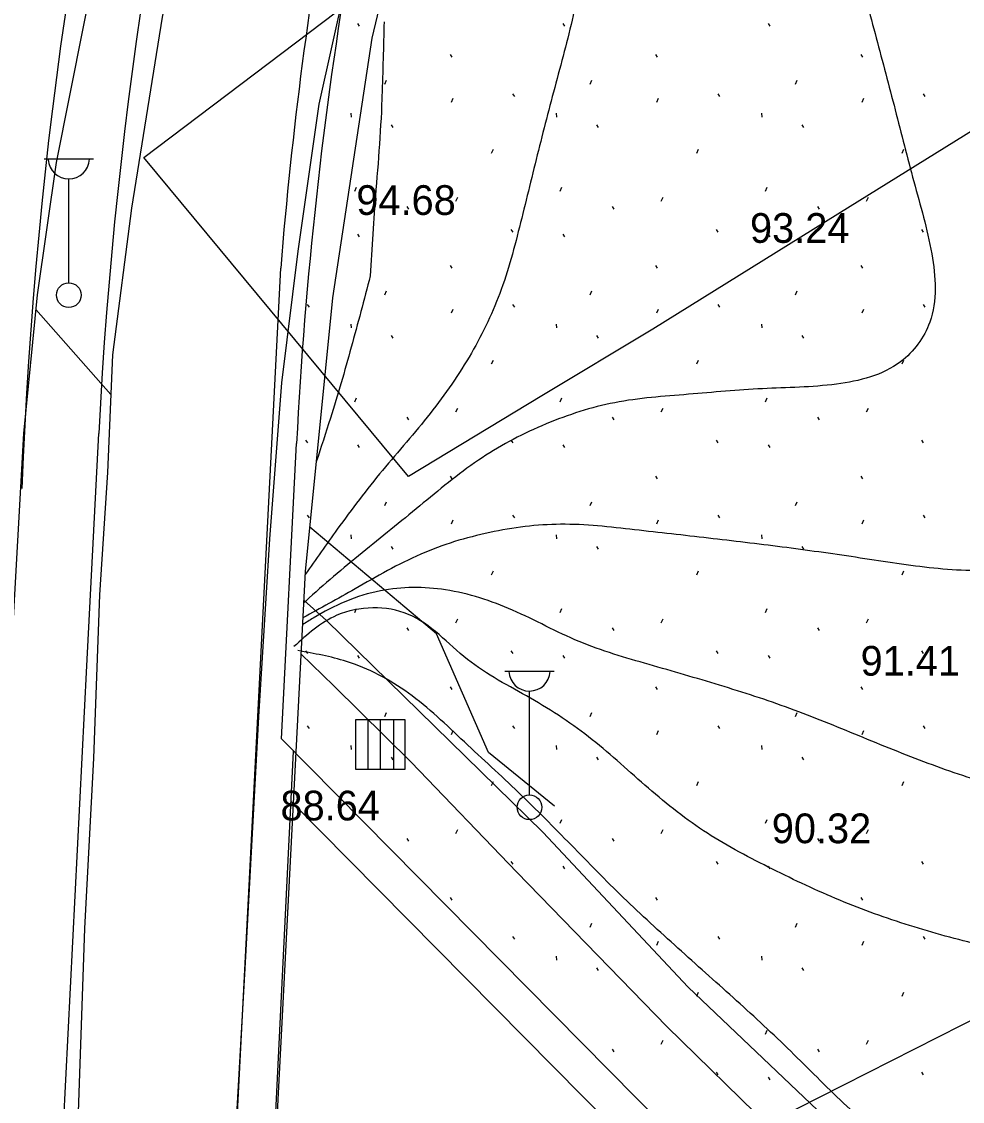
# Model space of a CAD drawing. Extents: x 412225 to 413380, y 4456471 to 4457189.
# Drawn here: x 412668.22 to 412706.22, y 4456722.27 to 4456765.88 of the extents above; entities that cross this region are included whole.
import ezdxf

# ---------------------------------------------------------------- set-up
doc = ezdxf.new("R2010")
doc.units = 0
for name, color, linetype in [('0_HALİHAZIR', 7, 'Continuous'), ('0_KADASTRO', 7, 'Continuous'), ('Level 41', 7, 'Continuous'), ('Level 62', 7, 'Continuous')]:
    doc.layers.add(name, color=color, linetype=linetype)

msp = doc.modelspace()

# ---------------------------------------------------------------- linework, layer by layer
at = {"layer": '0_HALİHAZIR'}
for p, q in [((412669.131, 4456760.333), (412671.131, 4456760.333)), ((412670.131, 4456755.333), (412670.131, 4456759.526)), ((412682.492, 4456758.569), (412682.308, 4456755.611)), ((412687.738, 4456739.651), (412689.738, 4456739.651)), ((412688.738, 4456734.651), (412688.738, 4456738.844)), ((412683.717, 4456737.684), (412681.717, 4456737.684)), ((412681.717, 4456737.684), (412681.717, 4456735.684)), ((412683.717, 4456737.684), (412681.717, 4456737.684)), ((412681.717, 4456737.684), (412681.717, 4456735.684)), ((412682.222, 4456735.684), (412682.222, 4456737.684)), ((412682.717, 4456735.684), (412682.717, 4456737.684)), ((412683.265, 4456735.684), (412683.265, 4456737.684)), ((412683.717, 4456735.684), (412683.717, 4456737.684)), ((412683.717, 4456735.684), (412683.717, 4456737.684)), ((412681.717, 4456735.684), (412683.717, 4456735.684)), ((412681.717, 4456735.684), (412683.717, 4456735.684))]:
    msp.add_line(p, q, dxfattribs=at)
for points in [[(412667.705, 4456738.404), (412668.319, 4456749.244), (412668.861, 4456754.841), (412669.638, 4456760.194), (412671.826, 4456771.222), (412673.519, 4456777.969), (412675.417, 4456784.177), (412677.82, 4456790.656), (412680.764, 4456798.407), (412683.199, 4456803.834), (412686.955, 4456811.642), (412691.094, 4456818.38), (412696.148, 4456825.735), (412699.773, 4456830.686), (412704.115, 4456836.108), (412708.688, 4456841.501), (412715.879, 4456848.789), (412726.186, 4456857.727), (412735.602, 4456865.198), (412750.205, 4456876.525), (412762.02, 4456885.738), (412775.183, 4456895.99), (412775.364, 4456896.141)], [(412684.648, 4456799.81), (412681.991, 4456793.804), (412680.12, 4456789.142), (412678.212, 4456783.624), (412676.557, 4456777.683), (412674.837, 4456770.524), (412673.9, 4456766.056), (412672.665, 4456758.345), (412671.898, 4456752.417), (412671.688, 4456747.664), (412671.366, 4456742.728), (412671.134, 4456736.134), (412670.758, 4456729.258), (412670.505, 4456721.841)], [(412742.95, 4456768.054), (412742.709, 4456772.16), (412741.745, 4456776.255), (412740.013, 4456781.161), (412737.651, 4456785.317), (412735.352, 4456788.538), (412732.317, 4456791.501), (412728.579, 4456794.241), (412724.985, 4456796.111), (412720.885, 4456797.711), (412716.226, 4456798.251), (412711.867, 4456798.434), (412706.537, 4456797.665), (412702.626, 4456796.458), (412698.189, 4456794.174), (412694.709, 4456791.591), (412690.527, 4456787.602), (412688.224, 4456784.396), (412687.256, 4456781.998), (412683.814, 4456771.248), (412682.374, 4456765.211), (412680.786, 4456754.718)], [(412697.453, 4456795.517), (412694.9, 4456793.639), (412691.148, 4456790.576), (412688.107, 4456787.244), (412686.438, 4456784.458), (412685.05, 4456780.461), (412683.352, 4456775.225), (412681.838, 4456769.746), (412680.234, 4456762.54), (412679.384, 4456756.61), (412678.722, 4456751.292), (412678.239, 4456744.989), (412677.786, 4456737.8), (412677.257, 4456727.881), (412676.433, 4456713.438)], [(412680.786, 4456754.718), (412679.682, 4456743.672), (412678.182, 4456714.804), (412676.891, 4456689.605), (412675.965, 4456668.667), (412674.91, 4456650.901), (412674.029, 4456632.544), (412673.304, 4456622.54), (412672.579, 4456615.955), (412671.095, 4456608.422), (412669.559, 4456601.069)], [(412671.827, 4456750.815), (412668.804, 4456754.253)], [(412744.221, 4456750.848), (412744.627, 4456745.627), (412744.52, 4456741.68), (412744.187, 4456738.618), (412743.007, 4456735.034), (412741.225, 4456731.014), (412738.205, 4456726.236), (412735.858, 4456723.736), (412732.659, 4456721.076), (412728.924, 4456719.082), (412724.248, 4456717.386), (412720.135, 4456716.553), (412714.255, 4456716.237), (412710.318, 4456716.87), (412705.381, 4456718.359), (412702.879, 4456719.736), (412700.365, 4456721.918), (412695.148, 4456726.887), (412689.271, 4456733.146), (412680.533, 4456741.696), (412679.621, 4456742.512)], [(412689.751, 4456734.194), (412687.089, 4456736.357), (412684.981, 4456741.158), (412679.86, 4456745.461)], [(412680.836, 4456739.057), (412679.509, 4456740.353)], [(412688.233, 4456731.526), (412683.96, 4456735.967), (412680.836, 4456739.057)], [(412688.233, 4456731.526), (412694.29, 4456725.303), (412698.443, 4456721.239)]]:
    msp.add_lwpolyline(points, dxfattribs=at)
for centre in [(412670.131, 4456754.833), (412688.738, 4456734.151)]:
    msp.add_circle(centre, 0.5, dxfattribs=at)
for centre in [(412670.131, 4456760.363), (412688.738, 4456739.681)]:
    msp.add_arc(centre, 0.837, 183.298, 356.9072, dxfattribs=at)
for points in [[(412704.847, 4456799.043), (412705.974, 4456796.274), (412707.165, 4456793.522), (412708.403, 4456790.789), (412709.584, 4456788.033), (412710.679, 4456785.242), (412711.666, 4456782.41), (412712.542, 4456779.544), (412713.326, 4456776.649), (412714.047, 4456773.737), (412714.748, 4456770.82), (412715.437, 4456767.9), (412716.115, 4456764.978), (412716.737, 4456762.044), (412717.218, 4456759.09), (412717.479, 4456756.11), (412717.34, 4456753.142), (412716.635, 4456750.305), (412715.242, 4456747.748), (412713.201, 4456745.661), (412710.668, 4456744.282), (412707.846, 4456743.729), (412704.882, 4456743.826), (412701.912, 4456744.245), (412698.942, 4456744.659), (412695.964, 4456745.019), (412692.983, 4456745.358), (412689.997, 4456745.579), (412687.132, 4456745.247), (412684.343, 4456744.37), (412681.692, 4456742.971), (412679.584, 4456741.797)], [(412695.675, 4456794.209), (412696.043, 4456791.246), (412696.342, 4456788.264), (412696.806, 4456785.324), (412697.548, 4456782.447), (412698.52, 4456779.61), (412699.468, 4456776.765), (412700.337, 4456773.894), (412701.167, 4456771.011), (412701.965, 4456768.119), (412702.742, 4456765.222), (412703.508, 4456762.321), (412704.263, 4456759.418), (412704.983, 4456756.506), (412704.904, 4456753.738), (412703.727, 4456752.143), (412701.142, 4456751.24), (412698.148, 4456751.055), (412695.157, 4456750.827), (412692.179, 4456750.49), (412689.408, 4456749.631), (412686.828, 4456748.268), (412684.45, 4456746.44), (412682.125, 4456744.545), (412679.841, 4456742.606), (412679.616, 4456742.397)], [(412731.677, 4456792.764), (412730.692, 4456789.931), (412729.801, 4456787.069), (412729.109, 4456784.16), (412728.851, 4456781.21), (412729.104, 4456778.277), (412729.838, 4456775.384), (412730.8, 4456772.544), (412731.778, 4456769.709), (412732.574, 4456766.828), (412732.856, 4456763.906), (412732.642, 4456760.965), (412732.023, 4456758.031), (412731.319, 4456755.115), (412730.582, 4456752.207), (412729.81, 4456749.308), (412728.974, 4456746.428), (412727.897, 4456743.648), (412726.427, 4456741.094), (412724.426, 4456738.95), (412722.007, 4456737.271), (412719.303, 4456736.01), (412716.459, 4456735.098), (412713.534, 4456734.546), (412710.577, 4456734.497), (412707.677, 4456735.005), (412704.835, 4456735.924), (412702.048, 4456737.034), (412699.259, 4456738.14), (412696.419, 4456739.078), (412693.569, 4456739.915), (412690.743, 4456740.845), (412688.057, 4456742.109), (412685.351, 4456742.931), (412682.725, 4456742.895), (412680.002, 4456741.793), (412679.57, 4456741.518)], [(412687.47, 4456780.884), (412688.574, 4456778.095), (412689.663, 4456775.299), (412690.551, 4456772.446), (412690.867, 4456769.607), (412690.606, 4456766.674), (412689.901, 4456763.759), (412689.145, 4456760.856), (412688.423, 4456757.945), (412687.6, 4456755.067), (412686.391, 4456752.494), (412684.724, 4456750.052), (412682.799, 4456747.755), (412680.974, 4456745.378), (412679.675, 4456743.547)], [(412682.863, 4456765.868), (412682.78, 4456762.873), (412682.776, 4456762.759), (412682.492, 4456758.569)], [(412745.325, 4456760.007), (412744.674, 4456757.08), (412743.93, 4456754.173), (412743.171, 4456751.271), (412742.421, 4456748.366), (412739.332, 4456740.016), (412738.051, 4456737.304), (412736.799, 4456734.578), (412735.403, 4456731.923), (412730.489, 4456728.959), (412727.571, 4456728.261), (412724.67, 4456727.498), (412718.811, 4456726.642), (412715.827, 4456726.941), (412712.857, 4456727.363), (412709.907, 4456727.907), (412706.982, 4456728.574), (412704.091, 4456729.374), (412701.272, 4456730.396), (412698.548, 4456731.652), (412695.923, 4456733.103), (412693.541, 4456734.919), (412691.275, 4456736.881), (412688.784, 4456738.552), (412686.229, 4456740.125), (412683.848, 4456741.941), (412680.963, 4456741.903), (412679.22, 4456740.639)], [(412682.308, 4456755.611), (412681.537, 4456752.727), (412680.695, 4456749.859), (412680.124, 4456748.102)], [(412726.577, 4456718.634), (412723.677, 4456717.874), (412720.747, 4456717.289), (412717.774, 4456716.956), (412714.8, 4456717.011), (412711.836, 4456717.352), (412708.916, 4456718.02), (412706.106, 4456718.981), (412703.552, 4456720.437), (412701.29, 4456722.332), (412699.154, 4456724.429), (412696.964, 4456726.464), (412694.732, 4456728.464), (412692.535, 4456730.5), (412690.421, 4456732.628), (412688.299, 4456734.749), (412686.108, 4456736.792), (412683.849, 4456738.76), (412681.341, 4456740.04), (412679.384, 4456740.477)]]:
    msp.add_spline(points, degree=3, dxfattribs=at)
at = {"layer": '0_KADASTRO'}
for points in [[(412673.155, 4456760.386), (412710.52, 4456788.649), (412718.832, 4456794.936), (412724.702, 4456799.376), (412733.822, 4456806.36), (412736.373, 4456808.313), (412748.14, 4456817.324), (412752.117, 4456820.369), (412752.765, 4456820.865), (412764.736, 4456830.001), (412767.728, 4456825.718), (412770.674, 4456821.667), (412779.346, 4456806.615), (412763.366, 4456796.695), (412758.704, 4456793.802), (412755.666, 4456791.916), (412701.697, 4456758.415), (412693.721, 4456753.465), (412689.243, 4456750.764), (412683.853, 4456747.515)], [(412691.873, 4456718.1), (412706.213, 4456725.36), (412710.904, 4456727.735), (412715.66, 4456730.142), (412730.796, 4456737.805), (412731.276, 4456736.996), (412735.606, 4456729.684), (412742.529, 4456717.995), (412747.23, 4456710.057), (412729.251, 4456700.211), (412717.055, 4456693.532)]]:
    msp.add_lwpolyline(points, close=True, dxfattribs=at)
at = {"layer": 'Level 41'}
for p, q in [((412681.794, 4456765.806), (412681.865, 4456765.699)), ((412690.087, 4456765.806), (412690.158, 4456765.699)), ((412698.38, 4456765.806), (412698.451, 4456765.699)), ((412685.532, 4456764.545), (412685.603, 4456764.438)), ((412693.825, 4456764.545), (412693.896, 4456764.438)), ((412702.118, 4456764.545), (412702.189, 4456764.438)), ((412682.891, 4456763.352), (412682.962, 4456763.511)), ((412691.184, 4456763.352), (412691.255, 4456763.511)), ((412699.477, 4456763.352), (412699.548, 4456763.511)), ((412685.59, 4456762.623), (412685.662, 4456762.783)), ((412688.055, 4456762.968), (412688.126, 4456762.861)), ((412693.883, 4456762.623), (412693.955, 4456762.783)), ((412696.348, 4456762.968), (412696.419, 4456762.861)), ((412702.176, 4456762.623), (412702.248, 4456762.783)), ((412704.641, 4456762.968), (412704.712, 4456762.861)), ((412681.52, 4456762.177), (412681.538, 4456762.017)), ((412689.813, 4456762.177), (412689.831, 4456762.017)), ((412698.106, 4456762.177), (412698.124, 4456762.017)), ((412683.15, 4456761.707), (412683.22, 4456761.6)), ((412691.443, 4456761.707), (412691.513, 4456761.6)), ((412699.736, 4456761.707), (412699.806, 4456761.6)), ((412687.206, 4456760.563), (412687.278, 4456760.723)), ((412695.499, 4456760.563), (412695.571, 4456760.723)), ((412703.792, 4456760.563), (412703.864, 4456760.723)), ((412681.685, 4456759.033), (412681.755, 4456759.193)), ((412689.978, 4456759.033), (412690.048, 4456759.193)), ((412698.271, 4456759.033), (412698.341, 4456759.193)), ((412685.768, 4456758.625), (412685.839, 4456758.785)), ((412694.061, 4456758.625), (412694.132, 4456758.785)), ((412702.354, 4456758.625), (412702.425, 4456758.785)), ((412683.78, 4456758.417), (412683.851, 4456758.311)), ((412692.073, 4456758.417), (412692.144, 4456758.311)), ((412700.366, 4456758.417), (412700.437, 4456758.311)), ((412687.988, 4456757.488), (412688.059, 4456757.381)), ((412696.281, 4456757.488), (412696.352, 4456757.381)), ((412704.574, 4456757.488), (412704.645, 4456757.381)), ((412681.794, 4456757.296), (412681.865, 4456757.189)), ((412690.087, 4456757.296), (412690.158, 4456757.189)), ((412698.38, 4456757.296), (412698.451, 4456757.189)), ((412685.532, 4456756.035), (412685.603, 4456755.928)), ((412693.825, 4456756.035), (412693.896, 4456755.928)), ((412702.118, 4456756.035), (412702.189, 4456755.928)), ((412682.891, 4456754.842), (412682.962, 4456755.001)), ((412691.184, 4456754.842), (412691.255, 4456755.001)), ((412699.477, 4456754.842), (412699.548, 4456755.001)), ((412679.762, 4456754.458), (412679.833, 4456754.351)), ((412685.59, 4456754.113), (412685.662, 4456754.273)), ((412688.055, 4456754.458), (412688.126, 4456754.351)), ((412693.883, 4456754.113), (412693.955, 4456754.273)), ((412696.348, 4456754.458), (412696.419, 4456754.351)), ((412702.176, 4456754.113), (412702.248, 4456754.273)), ((412704.641, 4456754.458), (412704.712, 4456754.351)), ((412681.52, 4456753.667), (412681.538, 4456753.507)), ((412689.813, 4456753.667), (412689.831, 4456753.507)), ((412698.106, 4456753.667), (412698.124, 4456753.507)), ((412683.15, 4456753.197), (412683.22, 4456753.09)), ((412691.443, 4456753.197), (412691.513, 4456753.09)), ((412699.736, 4456753.197), (412699.806, 4456753.09)), ((412687.206, 4456752.053), (412687.278, 4456752.213)), ((412695.499, 4456752.053), (412695.571, 4456752.213)), ((412703.792, 4456752.053), (412703.864, 4456752.213)), ((412681.685, 4456750.523), (412681.755, 4456750.683)), ((412689.978, 4456750.523), (412690.048, 4456750.683)), ((412698.271, 4456750.523), (412698.341, 4456750.683)), ((412683.78, 4456749.907), (412683.851, 4456749.801)), ((412685.768, 4456750.115), (412685.839, 4456750.275)), ((412692.073, 4456749.907), (412692.144, 4456749.801)), ((412694.061, 4456750.115), (412694.132, 4456750.275)), ((412700.366, 4456749.907), (412700.437, 4456749.801)), ((412702.354, 4456750.115), (412702.425, 4456750.275)), ((412679.695, 4456748.978), (412679.766, 4456748.871)), ((412681.794, 4456748.786), (412681.865, 4456748.679)), ((412687.988, 4456748.978), (412688.059, 4456748.871)), ((412690.087, 4456748.786), (412690.158, 4456748.679)), ((412696.281, 4456748.978), (412696.352, 4456748.871)), ((412698.38, 4456748.786), (412698.451, 4456748.679)), ((412704.574, 4456748.978), (412704.645, 4456748.871)), ((412685.532, 4456747.525), (412685.603, 4456747.418)), ((412693.825, 4456747.525), (412693.896, 4456747.418)), ((412702.118, 4456747.525), (412702.189, 4456747.418)), ((412682.891, 4456746.332), (412682.962, 4456746.491)), ((412691.184, 4456746.332), (412691.255, 4456746.491)), ((412699.477, 4456746.332), (412699.548, 4456746.491)), ((412679.762, 4456745.948), (412679.833, 4456745.841)), ((412685.59, 4456745.603), (412685.662, 4456745.763)), ((412688.055, 4456745.948), (412688.126, 4456745.841)), ((412693.883, 4456745.603), (412693.955, 4456745.763)), ((412696.348, 4456745.948), (412696.419, 4456745.841)), ((412702.176, 4456745.603), (412702.248, 4456745.763)), ((412704.641, 4456745.948), (412704.712, 4456745.841)), ((412681.52, 4456745.157), (412681.538, 4456744.997)), ((412689.813, 4456745.157), (412689.831, 4456744.997)), ((412698.106, 4456745.157), (412698.124, 4456744.997)), ((412683.15, 4456744.687), (412683.22, 4456744.58)), ((412691.443, 4456744.687), (412691.513, 4456744.58)), ((412699.736, 4456744.687), (412699.806, 4456744.58)), ((412687.206, 4456743.543), (412687.278, 4456743.703)), ((412695.499, 4456743.543), (412695.571, 4456743.703)), ((412703.792, 4456743.543), (412703.864, 4456743.703)), ((412681.685, 4456742.013), (412681.755, 4456742.173)), ((412689.978, 4456742.013), (412690.048, 4456742.173)), ((412698.271, 4456742.013), (412698.341, 4456742.173)), ((412685.768, 4456741.605), (412685.839, 4456741.765)), ((412694.061, 4456741.605), (412694.132, 4456741.765)), ((412702.354, 4456741.605), (412702.425, 4456741.765)), ((412683.78, 4456741.397), (412683.851, 4456741.291)), ((412692.073, 4456741.397), (412692.144, 4456741.291)), ((412700.366, 4456741.397), (412700.437, 4456741.291)), ((412679.695, 4456740.468), (412679.766, 4456740.361)), ((412687.988, 4456740.468), (412688.059, 4456740.361)), ((412696.281, 4456740.468), (412696.352, 4456740.361)), ((412704.574, 4456740.468), (412704.645, 4456740.361)), ((412681.794, 4456740.276), (412681.865, 4456740.169)), ((412690.087, 4456740.276), (412690.158, 4456740.169)), ((412698.38, 4456740.276), (412698.451, 4456740.169)), ((412685.532, 4456739.015), (412685.603, 4456738.908)), ((412693.825, 4456739.015), (412693.896, 4456738.908)), ((412702.118, 4456739.015), (412702.189, 4456738.908)), ((412682.891, 4456737.822), (412682.962, 4456737.981)), ((412691.184, 4456737.822), (412691.255, 4456737.981)), ((412699.477, 4456737.822), (412699.548, 4456737.981)), ((412679.762, 4456737.438), (412679.833, 4456737.331)), ((412688.055, 4456737.438), (412688.126, 4456737.331)), ((412696.348, 4456737.438), (412696.419, 4456737.331)), ((412704.641, 4456737.438), (412704.712, 4456737.331)), ((412685.59, 4456737.093), (412685.662, 4456737.253)), ((412693.883, 4456737.093), (412693.955, 4456737.253)), ((412702.176, 4456737.093), (412702.248, 4456737.253)), ((412681.52, 4456736.647), (412681.538, 4456736.487)), ((412689.813, 4456736.647), (412689.831, 4456736.487)), ((412698.106, 4456736.647), (412698.124, 4456736.487)), ((412683.15, 4456736.177), (412683.22, 4456736.07)), ((412691.443, 4456736.177), (412691.513, 4456736.07)), ((412699.736, 4456736.177), (412699.806, 4456736.07)), ((412687.206, 4456735.033), (412687.278, 4456735.193)), ((412695.499, 4456735.033), (412695.571, 4456735.193)), ((412703.792, 4456735.033), (412703.864, 4456735.193)), ((412689.978, 4456733.503), (412690.048, 4456733.663)), ((412698.271, 4456733.503), (412698.341, 4456733.663)), ((412685.768, 4456733.095), (412685.839, 4456733.255)), ((412694.061, 4456733.095), (412694.132, 4456733.255)), ((412702.354, 4456733.095), (412702.425, 4456733.255)), ((412683.78, 4456732.887), (412683.851, 4456732.781)), ((412692.073, 4456732.887), (412692.144, 4456732.781)), ((412700.366, 4456732.887), (412700.437, 4456732.781)), ((412687.988, 4456731.958), (412688.059, 4456731.851)), ((412690.087, 4456731.766), (412690.158, 4456731.659)), ((412696.281, 4456731.958), (412696.352, 4456731.851)), ((412698.38, 4456731.766), (412698.451, 4456731.659)), ((412704.574, 4456731.958), (412704.645, 4456731.851)), ((412685.532, 4456730.505), (412685.603, 4456730.398)), ((412693.825, 4456730.505), (412693.896, 4456730.398)), ((412702.118, 4456730.505), (412702.189, 4456730.398)), ((412691.184, 4456729.312), (412691.255, 4456729.471)), ((412699.477, 4456729.312), (412699.548, 4456729.471)), ((412688.055, 4456728.928), (412688.126, 4456728.821)), ((412693.883, 4456728.583), (412693.955, 4456728.743)), ((412696.348, 4456728.928), (412696.419, 4456728.821)), ((412702.176, 4456728.583), (412702.248, 4456728.743)), ((412704.641, 4456728.928), (412704.712, 4456728.821)), ((412689.813, 4456728.137), (412689.831, 4456727.977)), ((412698.106, 4456728.137), (412698.124, 4456727.977)), ((412691.443, 4456727.667), (412691.513, 4456727.56)), ((412699.736, 4456727.667), (412699.806, 4456727.56)), ((412695.499, 4456726.523), (412695.571, 4456726.683)), ((412703.792, 4456726.523), (412703.864, 4456726.683)), ((412698.271, 4456724.993), (412698.341, 4456725.153)), ((412694.061, 4456724.585), (412694.132, 4456724.745)), ((412702.354, 4456724.585), (412702.425, 4456724.745)), ((412692.073, 4456724.377), (412692.144, 4456724.271)), ((412700.366, 4456724.377), (412700.437, 4456724.271)), ((412696.281, 4456723.448), (412696.352, 4456723.341)), ((412704.574, 4456723.448), (412704.645, 4456723.341)), ((412698.38, 4456723.256), (412698.451, 4456723.149))]:
    msp.add_line(p, q, dxfattribs=at)
at = {"layer": 'Level 62'}
for p, q in [((412672.36, 4456631.831), (412678.688, 4456755.928)), ((412671.125, 4456745.066), (412671.338, 4456749.248)), ((412678.72, 4456736.909), (412679.328, 4456748.84)), ((412679.328, 4456748.84), (412679.328, 4456748.84)), ((412670.86, 4456739.858), (412671.125, 4456745.066)), ((412665.261, 4456630.078), (412670.86, 4456739.857)), ((412696.023, 4456719.418), (412678.72, 4456736.909)), ((412675.915, 4456670.121), (412679.211, 4456736.412)), ((412679.11, 4456734.381), (412694.987, 4456718.333))]:
    msp.add_line(p, q, dxfattribs=at)
for centre, radius, start, end in [((412849.607, 4456740.156), 181.5, 151.98121, 177.83282), ((412849.607, 4456740.156), 178.5, 151.98804, 177.08073), ((412849.678, 4456742.015), 171.555, 164.25967, 175.34821), ((412849.607, 4456740.156), 170.5, 163.65736, 177.08073), ((412716.314, 4456739.431), 30, 224.6913, 4.1759), ((412716.314, 4456739.431), 28.5, 224.6913, 4.1759)]:
    msp.add_arc(centre, radius, start, end, dxfattribs=at)

# ---------------------------------------------------------------- texts
at = {"layer": '0_HALİHAZIR'}
for s, p in [('94.68', (412681.745, 4456758.072)), ('93.24', (412697.645, 4456756.945)), ('91.41', (412702.111, 4456739.466)), ('88.64', (412678.681, 4456733.62)), ('90.32', (412698.524, 4456732.7))]:
    msp.add_text(s, height=1.2, dxfattribs=at).set_placement(p)

doc.saveas('drawing.dxf')
